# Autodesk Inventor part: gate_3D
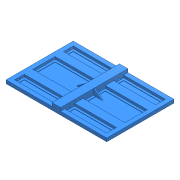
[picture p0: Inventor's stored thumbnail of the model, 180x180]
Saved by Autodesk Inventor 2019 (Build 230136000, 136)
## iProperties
Created: 2018-04
Part Number: gate_3D
Material: 一般
Document SubType Name: Modeling
Designer: ADJ
Density: 1 g/cm^3
Appearance: シアン
Mass: 26393.8 g
Surface Area: 24080.4 cm^2
Volume: 26393.8 cm^3
Author: ADJ
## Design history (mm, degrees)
derived "gate_skelton.ipt"
  sketch "スケッチ1"
    geometry: L1 (-600, 0)-(600, 0) reference; L2 (600, 0)-(600, 800) reference; L3 (600, 800)-(-600, 800) reference; L4 (-600, 800)-(-600, 0) reference; L5 (-550, 633.333)-(550, 633.333) reference; L6 (550, 533.333)-(-550, 533.333) reference; L7 (-550, 266.667)-(550, 266.667) reference; L8 (550, 166.667)-(-550, 166.667) reference; L9 (-50, 800)-(-50, 0) reference; L10 (50, 800)-(50, 0) reference; L11 (0, 0)-(0, 800) reference; L12 (-550, 750)-(550, 750) reference; L13 (550, 750)-(550, 50) reference; L14 (550, 50)-(-550, 50) reference; L15 (-550, 50)-(-550, 750) reference; L16 (-700, 0)-(700, 0) reference; L17 (700, 0)-(700, 2000) reference; L18 (700, 2000)-(-700, 2000) reference; L19 (-700, 2000)-(-700, 0) reference; L20 (0, 800)-(0, 3000) reference; 5 further points
extrude "押し出し1" new body sketch "スケッチ1" distance "d1" = 10; taper "d2" = 0 deg
extrude "押し出し2" join sketch "スケッチ1" distance "d3" = 70; taper "d4" = 0 deg
extrude "押し出し3" join sketch "スケッチ1" distance "d5" = 30; taper "d6" = 0 deg
hole "穴1" diameter "d9" = 50; stored, may be unused: countersink angle "d13" = 90 deg, drill point angle "d15" = 118 deg; dims "d7" = 35, "d8" = 50, "d10" = 6, "d11" = 4, "d12" = 2, "d14" = 100
sketch "スケッチ2"
  geometry: L1 (-40, 0)-(-40, 800) reference; L2 (-40, 800)-(0, 800) reference; L3 (0, 0)-(-40, 0) reference; 3 further points
  dimensions: "d16" = 20 distance from line of L1 point (-20, 700) (= 0.5 x d5 + 0.5 x d1); "d17" = 100 distance from line of L2 point (-20, 700); "d18" = 100 distance from line of L3 point (-20, 100) (= d17); "d19" = 20 distance from line of L1 point (-20, 100) (= d16)
hole "穴2" sketch "スケッチ2" at (-20, 100), (-20, 700) diameter "d20" = 20; stored, may be unused: countersink angle "d24" = 90 deg, drill point angle "d26" = 118 deg; dims "d21" = 6, "d22" = 4, "d23" = 2, "d25" = 8
sketch "スケッチ3"
  geometry: L1 (600, 800)-(-600, 800) reference; L2 (600, 0)-(600, 800) reference; L3 (-600, 0)-(600, 0) reference; L4 (-600, 800)-(-600, 0) reference; L5 (-550, 750)-(550, 750) reference; L6 (550, 750)-(550, 50) reference; L7 (550, 50)-(-550, 50) reference; L8 (-550, 50)-(-550, 750) reference; L9 (-575, 775)-(575, 775); L10 (575, 775)-(575, 25); L11 (575, 25)-(-575, 25); L12 (-575, 25)-(-575, 775); 1 further point
  constraints: 8 end point, 3 other
  dimensions: "d27" = 25 distance between parallel lines of L1 L9
extrude "押し出し4" join sketch "スケッチ3" distance "d28" = 20; taper "d29" = 0 deg
sketch "スケッチ4"
  geometry: L1 (-550, 750)-(550, 750) reference; L2 (-550, 50)-(-550, 750) reference; L3 (-550, 633.333)-(550, 633.333) reference; L4 (550, 533.333)-(-550, 533.333) reference; L5 (-550, 266.667)-(550, 266.667) reference; L6 (550, 166.667)-(-550, 166.667) reference; L7 (550, 50)-(-550, 50) reference; L8 (-50, 800)-(-50, 0) reference; L9 (550, 750)-(550, 50) reference; L10 (50, 800)-(50, 0) reference; L11 (-525, 725)-(-75, 725); L12 (-75, 725)-(-75, 658.333); L13 (-75, 658.333)-(-525, 658.333); L14 (-525, 658.333)-(-525, 725); L15 (-525, 508.333)-(-75, 508.333); L16 (-75, 508.333)-(-75, 291.667); L17 (-75, 291.667)-(-525, 291.667); L18 (-525, 291.667)-(-525, 508.333); L19 (-525, 141.667)-(-75, 141.667); L20 (-75, 141.667)-(-75, 75); L21 (-75, 75)-(-525, 75); L22 (-525, 75)-(-525, 141.667); L23 (75, 725)-(525, 725); L24 (525, 725)-(525, 658.333); L25 (525, 658.333)-(75, 658.333); L26 (75, 658.333)-(75, 725); L27 (75, 508.333)-(525, 508.333); L28 (525, 508.333)-(525, 291.667); L29 (525, 291.667)-(75, 291.667); L30 (75, 291.667)-(75, 508.333); L31 (75, 141.667)-(525, 141.667); L32 (525, 141.667)-(525, 75); L33 (525, 75)-(75, 75); L34 (75, 75)-(75, 141.667); 1 further point
  constraints: 48 end point, 14 point on line, 12 parallel, 6 horizontal, 6 perpendicular
  dimensions: "d30" = 25 distance between parallel lines of L14 L2; "d31" = 25 distance between parallel lines of L1 L11 (= d30); "d32" = 25 distance between parallel lines of L13 L3 (= d31); "d33" = 25 distance between parallel lines of L4 L15 (= d30); "d34" = 25 distance between parallel lines of L17 L5 (= d30); "d35" = 25 distance between parallel lines of L6 L19 (= d34); "d36" = 25 distance between parallel lines of L21 L7 (= d30); "d37" = 25 distance between parallel lines of L9 L24 (= d30); "d38" = 25 distance between parallel lines of L8 L12 (= d30); "d39" = 25 distance between parallel lines of L26 L10 (= d30)
extrude "押し出し5" cut sketch "スケッチ4" distance "d40" = 5; taper "d41" = 0 deg
node "作業平面1"
sketch "スケッチ5"
  geometry: L1 (50, 30)-(50, 70) reference; L2 (50, 0)-(50, 30) reference; L3 (50, 30)-(50, 0) reference; L4 (50, 20)-(50, 0) reference; L5 (50, 0)-(50, 30) reference; L6 (50, 30)-(50, 70) reference; L7 (50, 30)-(50, 70) reference; L8 (50, 30)-(50, 0) reference; L9 (50, 20)-(50, 0) reference; L10 (50, 0)-(50, 30) reference; L11 (50, 30)-(50, 0) reference; L12 (525, -5)-(75, -5) reference; L13 (525, 0)-(75, 0) reference; L14 (75, 0)-(525, 0) reference; L15 (550, 0)-(50, 0) reference; L16 (50, 0)-(550, 0) reference; L17 (75, 0)-(75, -5) reference; L18 (75, 0)-(75, -5) reference; L19 (50, 70)-(-50, 70) reference; L20 (-50, 70)-(50, 70) reference; L21 (50, 67.381)-(150, -5); 1 further point
  constraints: 2 end point, 2 point on line
  dimensions: "d42" = 100 horizontal distance of L21.start L21.end
feature "リブ1" sketch "スケッチ5" dims "d43" = 1, "d44" = 15, "d45" = 0, "d46" = 0, "d47" = 1, "d48" = 1
mirror "ミラー1"
node "ソリッド1"
node "投影ループ1"
node "投影ループ2"
node "投影ループ3"
node "投影ループ4"
